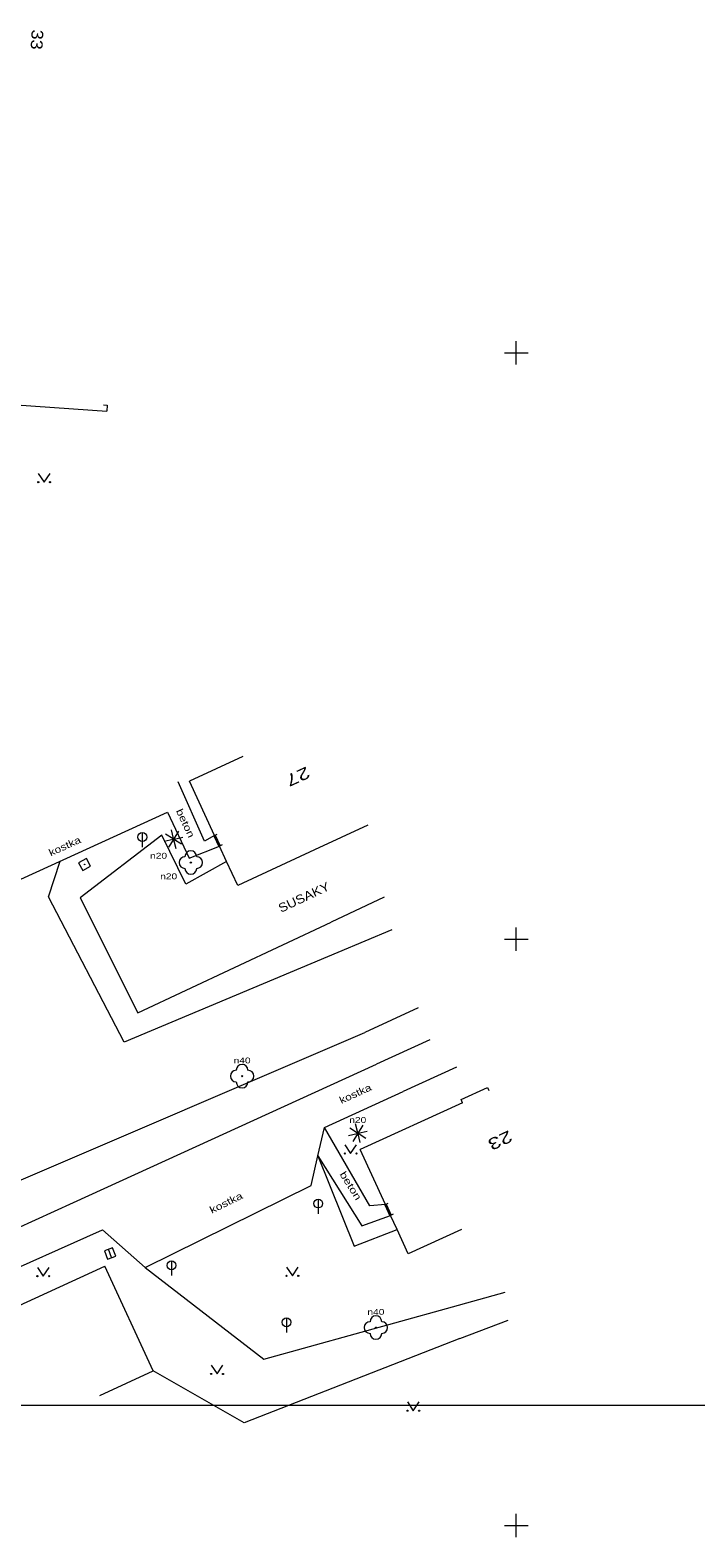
# Model space of a CAD drawing. Extents: x -670514 to -669423, y -1130798 to -1130123.
# Drawn here: x -670191.5 to -670134.7, y -1130401 to -1130272.5 of the extents above; entities that cross this region are included whole.
import ezdxf
from ezdxf.enums import TextEntityAlignment as Align

# ---------------------------------------------------------------- set-up
doc = ezdxf.new("R2010")
doc.units = 0
doc.header["$LTSCALE"] = 0.24
for name, color, linetype, lineweight in [('10', 7, 'Continuous', 13), ('14', 7, 'Continuous', 13), ('22', 7, 'Continuous', 13), ('26', 7, 'Continuous', 13), ('27', 7, 'Continuous', 13), ('36', 7, 'Continuous', 13), ('5', 7, 'Continuous', 13), ('6', 7, 'Continuous', 13), ('60', 7, 'Continuous', 13), ('61', 7, 'Continuous', 13)]:
    doc.layers.add(name, color=color, linetype=linetype, lineweight=lineweight)
for name, color, linetype in [('40', 7, 'Continuous'), ('42', 7, 'Continuous'), ('44', 7, 'Continuous')]:
    doc.layers.add(name, color=color, linetype=linetype)

msp = doc.modelspace()

# ---------------------------------------------------------------- linework, layer by layer
at = {"layer": '10'}
for p, q in [((-670197.261, -1130347.166), (-670179.752, -1130339.172)), ((-670157.38, -1130358.571), (-670161.928, -1130360.649)), ((-670187.75, -1130372.448), (-670161.928, -1130360.649)), ((-670155.096, -1130360.913), (-670159.644, -1130362.991)), ((-670223.892, -1130388.929), (-670187.75, -1130372.448))]:
    msp.add_line(p, q, dxfattribs=at)
for points in [[(-670175.738, -1130341.163), (-670176.577, -1130341.63), (-670178.833, -1130336.569)], [(-670179.752, -1130339.172), (-670177.892, -1130343.105), (-670175.302, -1130342.065)], [(-670195.226, -1130379.206), (-670185.29, -1130374.784), (-670181.64, -1130377.99), (-670167.487, -1130371.008), (-670166.91, -1130368.462), (-670166.367, -1130366.06), (-670159.644, -1130362.991)], [(-670161.16, -1130372.612), (-670162.483, -1130372.73), (-670166.367, -1130366.06)], [(-670166.91, -1130368.462), (-670163.17, -1130374.437), (-670160.721, -1130373.553)]]:
    msp.add_lwpolyline(points, dxfattribs=at)
at = {"layer": '14'}
for p, q in [((-670161.267, -1130346.415), (-670165.793, -1130348.539)), ((-670160.603, -1130349.211), (-670165.215, -1130351.142)), ((-670158.379, -1130355.866), (-670162.927, -1130357.944)), ((-670154.817, -1130384.042), (-670150.686, -1130382.484))]:
    msp.add_line(p, q, dxfattribs=at)
for points in [[(-670174.699, -1130343.383), (-670178.191, -1130345.307), (-670180.227, -1130341.135), (-670187.179, -1130346.479)], [(-670165.215, -1130351.142), (-670183.439, -1130358.772), (-670189.878, -1130346.388), (-670188.898, -1130343.348)], [(-670187.179, -1130346.479), (-670182.26, -1130356.268), (-670165.793, -1130348.539)], [(-670236.685, -1130360.389), (-670238.138, -1130367.12), (-670230.255, -1130380.975), (-670224.134, -1130384.194), (-670162.927, -1130357.944)], [(-670166.91, -1130368.462), (-670163.826, -1130376.166), (-670160.163, -1130374.743)], [(-670181.64, -1130377.99), (-670171.527, -1130385.813), (-670155.962, -1130381.496), (-670150.956, -1130380.107)], [(-670154.817, -1130384.042), (-670173.209, -1130391.239), (-670180.964, -1130386.804)]]:
    msp.add_lwpolyline(points, dxfattribs=at)
at = {"layer": '22'}
for p, q in [((-670180.018, -1130341.647), (-670179.264, -1130341.475)), ((-670179.258, -1130341.447), (-670179.914, -1130341.033)), ((-670179.244, -1130341.501), (-670179.658, -1130342.157)), ((-670179.232, -1130341.427), (-670179.404, -1130340.673)), ((-670179.216, -1130341.507), (-670179.044, -1130342.261)), ((-670178.79, -1130340.777), (-670179.204, -1130341.433)), ((-670178.534, -1130341.901), (-670179.19, -1130341.487)), ((-670179.184, -1130341.459), (-670178.43, -1130341.287)), ((-670163.527, -1130366.51), (-670163.699, -1130365.756)), ((-670163.085, -1130365.86), (-670163.499, -1130366.516)), ((-670164.313, -1130366.73), (-670163.559, -1130366.558)), ((-670163.553, -1130366.53), (-670164.209, -1130366.116)), ((-670163.539, -1130366.584), (-670163.953, -1130367.24)), ((-670163.511, -1130366.59), (-670163.339, -1130367.344)), ((-670162.829, -1130366.984), (-670163.485, -1130366.57)), ((-670163.479, -1130366.542), (-670162.725, -1130366.37))]:
    msp.add_line(p, q, dxfattribs=at)
for centre, radius in [((-670179.224, -1130341.467), 0.04), ((-670177.751, -1130343.469), 0.05), ((-670173.381, -1130361.676), 0.05), ((-670163.519, -1130366.55), 0.04), ((-670161.971, -1130383.118), 0.05)]:
    msp.add_circle(centre, radius, dxfattribs=at)
for centre, start, end in [((-670177.751, -1130342.969), 0, 180), ((-670178.251, -1130343.469), 90, 270), ((-670177.751, -1130343.969), 180, 0), ((-670177.251, -1130343.469), 270, 90), ((-670173.381, -1130361.176), 0, 180), ((-670173.881, -1130361.676), 90, 270), ((-670173.381, -1130362.176), 180, 0), ((-670172.881, -1130361.676), 270, 90), ((-670162.471, -1130383.118), 90, 270), ((-670161.971, -1130382.618), 0, 180), ((-670161.471, -1130383.118), 270, 90), ((-670161.971, -1130383.618), 180, 0)]:
    msp.add_arc(centre, 0.5, start, end, dxfattribs=at)
at = {"layer": '26'}
msp.add_lwpolyline([(-670187.319, -1130343.477), (-670186.962, -1130344.136), (-670186.303, -1130343.779), (-670186.66, -1130343.12)], close=True, dxfattribs=at)
msp.add_circle((-670186.811, -1130343.628), 0.02, dxfattribs=at)
at = {"layer": '27'}
for p, q in [((-670181.89, -1130340.913), (-670181.89, -1130342.163)), ((-670166.889, -1130372.168), (-670166.889, -1130373.418)), ((-670184.511, -1130377.147), (-670184.775, -1130376.445)), ((-670179.399, -1130377.438), (-670179.399, -1130378.688)), ((-670169.593, -1130382.292), (-670169.593, -1130383.542))]:
    msp.add_line(p, q, dxfattribs=at)
msp.add_lwpolyline([(-670184.161, -1130377.015), (-670184.425, -1130376.313), (-670185.127, -1130376.578), (-670184.863, -1130377.279)], close=True, dxfattribs=at)
for centre in [(-670181.8896, -1130341.2881), (-670166.8886, -1130372.5431), (-670179.3986, -1130377.8131), (-670169.5926, -1130382.6671)]:
    msp.add_circle(centre, 0.375, dxfattribs=at)
at = {"layer": '36'}
for points in [[(-670190.758, -1130310.285), (-670190.258, -1130311.035), (-670189.758, -1130310.285)], [(-670164.625, -1130367.53), (-670164.125, -1130368.28), (-670163.625, -1130367.53)], [(-670190.834, -1130377.986), (-670190.334, -1130378.736), (-670189.834, -1130377.986)], [(-670169.591, -1130377.953), (-670169.091, -1130378.703), (-670168.591, -1130377.953)], [(-670176.014, -1130386.324), (-670175.514, -1130387.074), (-670175.014, -1130386.324)], [(-670159.282, -1130389.457), (-670158.782, -1130390.207), (-670158.282, -1130389.457)]]:
    msp.add_lwpolyline(points, dxfattribs=at)
for centre in [(-670190.758, -1130311.035), (-670189.758, -1130311.035), (-670164.625, -1130368.28), (-670163.625, -1130368.28), (-670190.834, -1130378.736), (-670189.834, -1130378.736), (-670169.591, -1130378.703), (-670168.591, -1130378.703), (-670176.014, -1130387.074), (-670175.014, -1130387.074), (-670159.282, -1130390.207), (-670158.282, -1130390.207)]:
    msp.add_circle(centre, 0.05, dxfattribs=at)
at = {"layer": '5'}
for p, q in [((-670196.658, -1130304.168), (-670184.928, -1130304.963)), ((-670185.193, -1130304.444), (-670184.894, -1130304.464)), ((-670184.894, -1130304.464), (-670184.928, -1130304.963)), ((-670173.332, -1130334.432), (-670177.874, -1130336.523)), ((-670175.738, -1130341.163), (-670177.874, -1130336.523)), ((-670162.666, -1130340.287), (-670167.204, -1130342.386)), ((-670154.59, -1130363.942), (-670163.309, -1130367.934)), ((-670161.16, -1130372.612), (-670163.309, -1130367.934)), ((-670154.667, -1130374.764), (-670159.224, -1130376.822)), ((-670193.815, -1130381.88), (-670185.09, -1130377.885)), ((-670180.964, -1130386.804), (-670185.09, -1130377.885)), ((-670185.502, -1130388.903), (-670180.964, -1130386.804))]:
    msp.add_line(p, q, dxfattribs=at)
for points in [[(-670167.204, -1130342.386), (-670173.743, -1130345.41), (-670174.699, -1130343.383), (-670175.302, -1130342.065)], [(-670154.59, -1130363.942), (-670154.713, -1130363.674), (-670152.466, -1130362.658), (-670152.348, -1130362.915)], [(-670159.224, -1130376.822), (-670160.163, -1130374.743), (-670160.721, -1130373.553)]]:
    msp.add_lwpolyline(points, dxfattribs=at)
at = {"layer": '6'}
for p, q in [((-670175.738, -1130341.163), (-670175.512, -1130341.054)), ((-670175.076, -1130341.956), (-670175.302, -1130342.065)), ((-670161.16, -1130372.612), (-670160.933, -1130372.506)), ((-670160.494, -1130373.447), (-670160.721, -1130373.553))]:
    msp.add_line(p, q, dxfattribs=at)
at = {"layer": '6', "lineweight": 35}
for p, q in [((-670175.738, -1130341.163), (-670175.302, -1130342.065)), ((-670161.16, -1130372.612), (-670160.721, -1130373.553))]:
    msp.add_line(p, q, dxfattribs=at)
at = {"layer": '60'}
msp.add_lwpolyline([(-670513.627, -1130676.756), (-670103.627, -1130676.756), (-670103.627, -1130389.756), (-670513.627, -1130389.756)], close=True, dxfattribs=at)
at = {"layer": '61'}
for p, q in [((-670150, -1130301), (-670150, -1130299)), ((-670151, -1130300), (-670149, -1130300)), ((-670150, -1130351), (-670150, -1130349)), ((-670151, -1130350), (-670149, -1130350)), ((-670150, -1130401), (-670150, -1130399)), ((-670151, -1130400), (-670149, -1130400))]:
    msp.add_line(p, q, dxfattribs=at)

# ---------------------------------------------------------------- texts
at = {"layer": '22', "width": 1.3}
for s, p in [('n20', (-670180.5015, -1130343.136)), ('n20', (-670179.6415, -1130344.891)), ('n40', (-670173.3805, -1130360.59)), ('n20', (-670163.5195, -1130365.664)), ('n40', (-670161.9705, -1130382.032))]:
    msp.add_text(s, height=0.499, dxfattribs=at).set_placement(p, align=Align.CENTER)
at = {"layer": '40'}
for s, rotation, width, p in [('beton', 294.97, 1.3, (-670178.4838, -1130340.2354)), ('kostka', 24.541, 1.25, (-670188.3776, -1130342.3417)), ('kostka', 24.536, 1.25, (-670163.6016, -1130363.4488)), ('beton', 302.044, 1.35, (-670164.3805, -1130371.1848)), ('kostka', 26.258, 1.3, (-670174.6122, -1130372.7425))]:
    msp.add_text(s, height=0.6, rotation=rotation, dxfattribs=dict(at, width=width)).set_placement(p, align=Align.CENTER)
at = {"layer": '42', "width": 1.15}
msp.add_text('SUSAKY', height=0.75, rotation=25.144, dxfattribs=at).set_placement((-670167.9498, -1130346.7602), align=Align.CENTER)
at = {"layer": '44'}
for s, rotation, width, p in [('33', 266.601, 1.15, (-670191.3628, -1130273.2689)), ('27', 204.595, 1.4, (-670168.8309, -1130335.6826)), ('23', 204.857, 1.4, (-670151.5823, -1130366.7069))]:
    msp.add_text(s, height=1, rotation=rotation, dxfattribs=dict(at, width=width)).set_placement(p, align=Align.CENTER)

doc.saveas('drawing.dxf')
